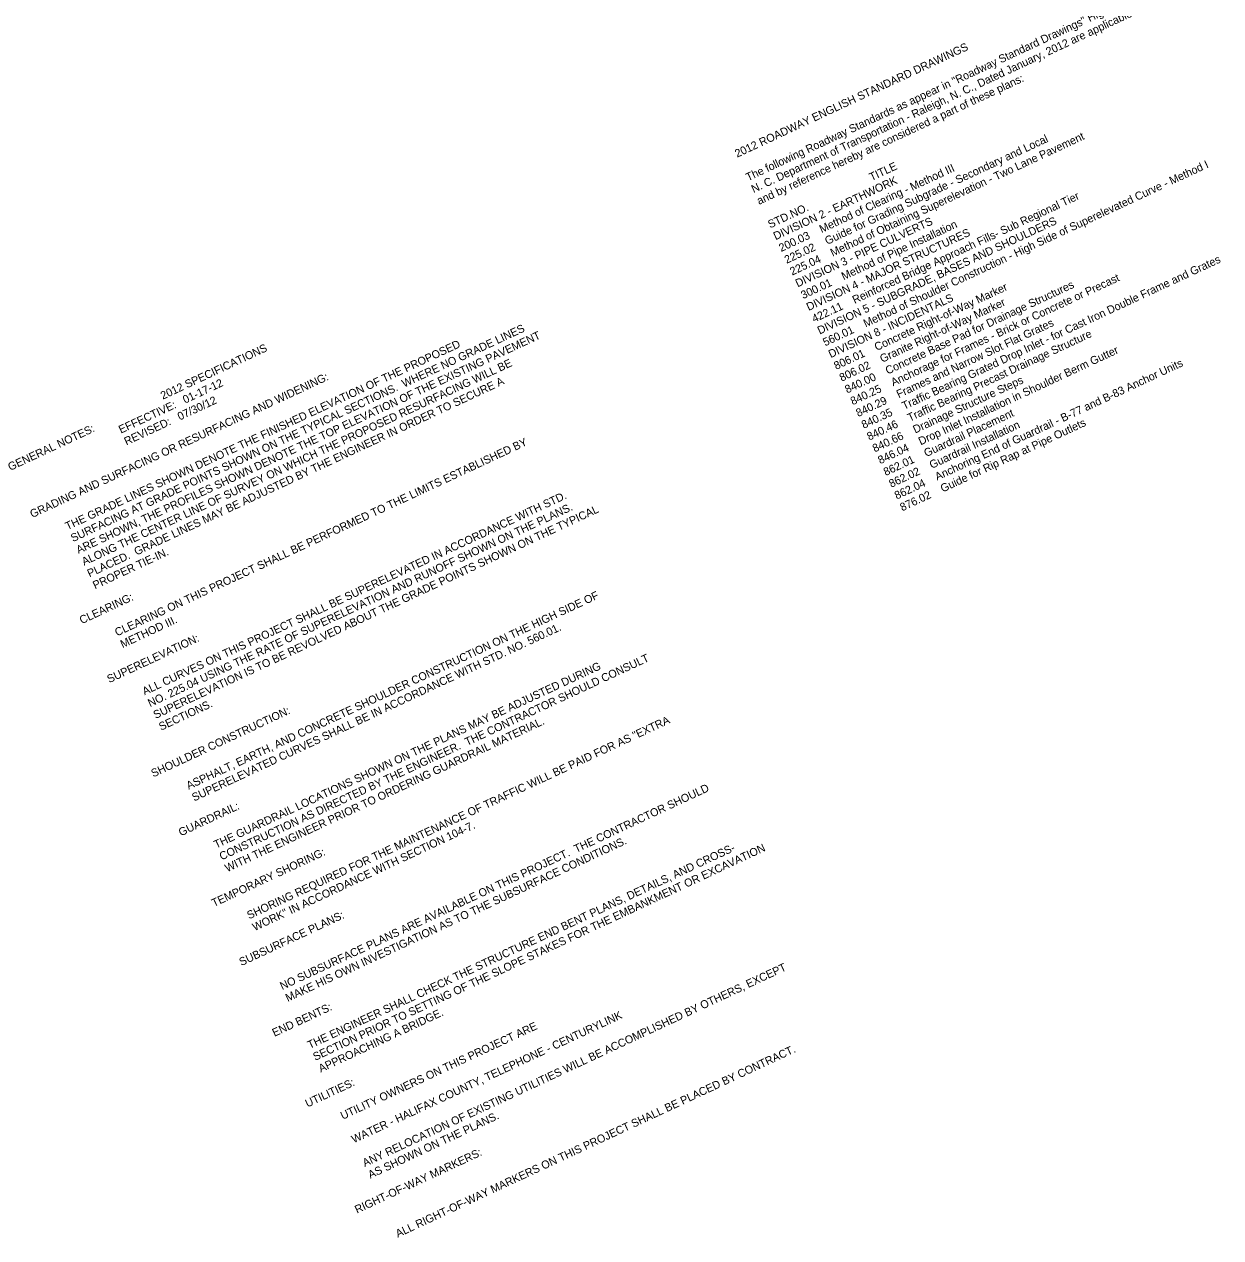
# Model space of a CAD drawing. Extents: x 2321368 to 2323356, y 919896 to 921600.
# Drawn here: x 2322104 to 2322820, y 920471 to 921198 of the extents above; entities that cross this region are included whole.
import ezdxf

# ---------------------------------------------------------------- set-up
doc = ezdxf.new("R2010")
doc.units = 0
doc.layers.add('Default', color=7, linetype='Continuous')

msp = doc.modelspace()

# ---------------------------------------------------------------- texts
at = {"layer": 'Default'}
for s, p in [('The following Roadway Standards as appear in "Roadway Standard Drawings" Highway Design Branch -', (2322537.3, 921104.08)), ('N. C. Department of Transportation - Raleigh, N. C., Dated January, 2012 are applicable to this project', (2322540.59, 921097.01)), ('2012 ROADWAY ENGLISH STANDARD DRAWINGS', (2322530.7, 921118.21)), ('and by reference hereby are considered a part of these plans:', (2322543.89, 921089.94)), ('225.02    Guide for Grading Subgrade - Secondary and Local', (2322560.39, 921054.6)), ('225.04    Method of Obtaining Superelevation - Two Lane Pavement', (2322563.69, 921047.53)), ('STD.NO.                       TITLE', (2322550.49, 921075.8)), ('200.03    Method of Clearing - Method III', (2322557.09, 921061.67)), ('560.01    Method of Shoulder Construction - High Side of Superelevated Curve - Method I', (2322583.48, 921005.12)), ('DIVISION 2 - EARTHWORK', (2322553.79, 921068.74)), ('422.11    Reinforced Bridge Approach Fills- Sub Regional Tier', (2322576.88, 921019.26)), ('DIVISION 3 - PIPE CULVERTS', (2322566.98, 921040.46)), ('300.01    Method of Pipe Installation ', (2322570.28, 921033.39)), ('DIVISION 5 - SUBGRADE, BASES AND SHOULDERS', (2322580.18, 921012.19)), ('DIVISION 4 - MAJOR STRUCTURES', (2322573.58, 921026.33)), ('840.35    Traffic Bearing Grated Drop Inlet - for Cast Iron Double Frame and Grates', (2322606.57, 920955.65)), ('840.25    Anchorage for Frames - Brick or Concrete or Precast', (2322599.97, 920969.78)), ('806.01    Concrete Right-of-Way Marker', (2322590.07, 920990.99)), ('840.00    Concrete Base Pad for Drainage Structures', (2322596.67, 920976.85)), ('DIVISION 8 - INCIDENTALS', (2322586.78, 920998.05)), ('806.02    Granite Right-of-Way Marker', (2322593.37, 920983.92)), ('840.29    Frames and Narrow Slot Flat Grates', (2322603.27, 920962.71)), ('         SURFACING AT GRADE POINTS SHOWN ON THE TYPICAL SECTIONS.  WHERE NO GRADE LINES ', (2322118.24, 920880.95)), ('         ARE SHOWN, THE PROFILES SHOWN DENOTE THE TOP ELEVATION OF THE EXISTING PAVEMENT ', (2322121.54, 920873.88)), ('840.46    Traffic Bearing Precast Drainage Structure', (2322609.87, 920948.58)), ('GENERAL NOTES:                         2012 SPECIFICATIONS', (2322095.15, 920930.43)), ('         THE GRADE LINES SHOWN DENOTE THE FINISHED ELEVATION OF THE PROPOSED ', (2322114.94, 920888.02)), ('846.04    Drop Inlet Installation in Shoulder Berm Gutter', (2322616.46, 920934.44)), ('         ALONG THE CENTER LINE OF SURVEY ON WHICH THE PROPOSED RESURFACING WILL BE ', (2322124.84, 920866.82)), ('862.04    Anchoring End of Guardrail - B-77 and B-83 Anchor Units', (2322626.36, 920913.24)), ('GRADING AND SURFACING OR RESURFACING AND WIDENING:  ', (2322108.35, 920902.16)), ('         PLACED.  GRADE LINES MAY BE ADJUSTED BY THE ENGINEER IN ORDER TO SECURE A ', (2322128.14, 920859.75)), ('                                       EFFECTIVE:   01-17-12', (2322098.45, 920923.36)), ('840.66    Drainage Structure Steps', (2322613.17, 920941.51)), ('                                       REVISED:   07/30/12', (2322101.75, 920916.29)), ('862.01    Guardrail Placement', (2322619.76, 920927.37)), ('876.02    Guide for Rip Rap at Pipe Outlets', (2322629.66, 920906.17)), ('862.02    Guardrail Installation', (2322623.06, 920920.3)), ('         CLEARING ON THIS PROJECT SHALL BE PERFORMED TO THE LIMITS ESTABLISHED BY ', (2322144.63, 920824.41)), ('         ALL CURVES ON THIS PROJECT SHALL BE SUPERELEVATED IN ACCORDANCE WITH STD. ', (2322161.13, 920789.07)), ('         NO. 225.04 USING THE RATE OF SUPERELEVATION AND RUNOFF SHOWN ON THE PLANS.', (2322164.43, 920782)), ('         SUPERELEVATION IS TO BE REVOLVED ABOUT THE GRADE POINTS SHOWN ON THE TYPICAL ', (2322167.72, 920774.93)), ('         PROPER TIE-IN.  ', (2322131.44, 920852.68)), ('CLEARING:  ', (2322138.04, 920838.54)), ('         ASPHALT, EARTH, AND CONCRETE SHOULDER CONSTRUCTION ON THE HIGH SIDE OF', (2322187.52, 920732.52)), ('         METHOD III.', (2322147.93, 920817.34)), ('         SUPERELEVATED CURVES SHALL BE IN ACCORDANCE WITH STD. NO. 560.01.', (2322190.82, 920725.45)), ('SUPERELEVATION:  ', (2322154.53, 920803.2)), ('         THE GUARDRAIL LOCATIONS SHOWN ON THE PLANS MAY BE ADJUSTED DURING ', (2322204.01, 920697.18)), ('         CONSTRUCTION AS DIRECTED BY THE ENGINEER.  THE CONTRACTOR SHOULD CONSULT', (2322207.31, 920690.11)), ('SHOULDER CONSTRUCTION:  ', (2322180.92, 920746.66)), ('         SECTIONS.  ', (2322171.02, 920767.86)), ('         WITH THE ENGINEER PRIOR TO ORDERING GUARDRAIL MATERIAL.', (2322210.61, 920683.05)), ('         SHORING REQUIRED FOR THE MAINTENANCE OF TRAFFIC WILL BE PAID FOR AS "EXTRA ', (2322223.8, 920654.77)), ('         NO SUBSURFACE PLANS ARE AVAILABLE ON THIS PROJECT.  THE CONTRACTOR SHOULD ', (2322243.59, 920612.36)), ('GUARDRAIL:  ', (2322197.41, 920711.32)), ('         WORK" IN ACCORDANCE WITH SECTION 104-7.  ', (2322227.1, 920647.7)), ('         MAKE HIS OWN INVESTIGATION AS TO THE SUBSURFACE CONDITIONS.  ', (2322246.89, 920605.3)), ('         SECTION PRIOR TO SETTING OF THE SLOPE STAKES FOR THE EMBANKMENT OR EXCAVATION ', (2322263.39, 920569.96)), ('TEMPORARY SHORING:  ', (2322217.2, 920668.91)), ('         THE ENGINEER SHALL CHECK THE STRUCTURE END BENT PLANS, DETAILS, AND CROSS-', (2322260.09, 920577.02)), ('SUBSURFACE PLANS:  ', (2322233.7, 920633.57)), ('         ANY RELOCATION OF EXISTING UTILITIES WILL BE ACCOMPLISHED BY OTHERS, EXCEPT ', (2322293.08, 920506.34)), ('END BENTS:  ', (2322253.49, 920591.16)), ('         APPROACHING A BRIDGE.  ', (2322266.69, 920562.89)), ('         WATER - HALIFAX COUNTY, TELEPHONE - CENTURYLINK', (2322286.48, 920520.48)), ('         UTILITY OWNERS ON THIS PROJECT ARE ', (2322279.88, 920534.61)), ('         ALL RIGHT-OF-WAY MARKERS ON THIS PROJECT SHALL BE PLACED BY CONTRACT.  ', (2322312.87, 920463.93)), ('UTILITIES:  ', (2322273.28, 920548.75)), ('         AS SHOWN ON THE PLANS.  ', (2322296.37, 920499.27)), ('RIGHT-OF-WAY MARKERS:  ', (2322302.97, 920485.14))]:
    msp.add_text(s, height=4.8, rotation=25.01869, dxfattribs=at).set_placement(p)

doc.saveas('drawing.dxf')
